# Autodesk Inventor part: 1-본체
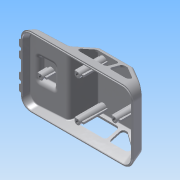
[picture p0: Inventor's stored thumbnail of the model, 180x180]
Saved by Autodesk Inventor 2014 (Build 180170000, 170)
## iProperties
Created: 2015-05
Part Number: 1-본체
Material: ABS 플라스틱
Document SubType Name: Modeling
Designer: Administrator
Density: 1.06 g/cm^3
Appearance: 매끄러움 - 흰색
Mass: 31.9513 g
Surface Area: 305.413 cm^2
Volume: 30.1428 cm^3
Author: Administrator
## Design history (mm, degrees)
sketch "스케치1"
  geometry: L1 (0, 0)-(122, 0); L2 (0, 0)-(2.144, 8); L3 (2.144, 8)-(42, 10.089); L4 (42, 10.089)-(54.442, 30); L5 (54.442, 30)-(92, 30); L6 (92, 30)-(118.738, 12.175); L7 (118.738, 12.175)-(122, 0); L8 (118.738, 12.175)-(122, 10); L9 (122, 10)-(122, 0)
  constraints: 18 end point, 1 collinear, 1 horizontal, 1 parallel, 1 perpendicular
  dimensions: "d0" = 122 distance of L1.start L1.end; "d1" = 8 distance from line of L1 L2.end; "d2" = 105 deg angle of L1 L2; "d3" = 42 horizontal distance of L1.start L3.end; "d4" = 30 horizontal distance of L1.end L5.end; "d6" = 30 horizontal distance of L1.end L5.end; "d7" = 3 deg angle of L1 L3; "d8" = 125 deg angle of L3 L4; "d9" = 20 vertical distance of L8.end L5.end; "d10" = 105 deg angle of L1 L7
extrude "돌출1" new body sketch "스케치1" stored distance "d11" = 76; taper "d12" = 0 deg
sketch "스케치2"
  geometry: L1 (8, 38)-(0, 38) reference; L2 (0, 38)-(0, -38) reference; L3 (0, 38)-(30, 38); L4 (30, 38)-(30, 29.962); L5 (30, 29.962)-(0, 38); L6 (30, -38)-(30, 38) reference; L7 (0, -38)-(30, -29.962); L8 (30, -38)-(0, -38); 1 further point
  constraints: 10 end point, 3 perpendicular, 1 collinear, 1 point on line
  dimensions: "d14" = 105 deg angle of L2 L5; "d51" = 105 deg angle of L2 L7
extrude "돌출2" cut sketch "스케치2" stored distance "d15" = 76; taper "d16" = 0 deg
sketch "스케치9"
  geometry: L1 (8.441, 48.856)-(28.441, 48.856); L2 (28.441, 48.856)-(28.441, 22.856); L3 (28.441, 22.856)-(8.441, 22.856); L4 (8.441, 22.856)-(8.441, 48.856); L5 (-2.559, -2.144)-(-2.559, 73.856) reference; 3 further points
  constraints: 8 end point, 2 midpoint, 2 parallel, 1 horizontal, 1 horizontal alignment, 1 perpendicular
  dimensions: "d59" = 11 distance between parallel lines of L4 L5; "d60" = 20 distance of L1.start L1.end; "d61" = 26 distance of L3.end L1.start
extrude "돌출7" join sketch "스케치9" distance "d62" = 5; taper "d63" = -20 deg
fillet "모깎기1" dims "d18" = 12, "d19" = 3
fillet "모깎기2" dims "d20" = 3
feature "쉘1" dims "d17" = 2
sketch "스케치3"
  geometry: L1 (91.092, 30)-(56.105, 30) reference; L2 (53.561, 28.59)-(42.828, 11.413) reference; L3 (81.84, 25)-(57.213, 25); L4 (57.213, 25)-(47.84, 10); L5 (47.84, 10)-(81.84, 10); L6 (81.84, 10)-(81.84, 25); L7 (84.986, 25)-(84.986, 10); L8 (84.986, 10)-(112.986, 10); L9 (107.213, 19.858)-(92.756, 29.496) reference; L10 (112.986, 10)-(90.486, 25); L11 (84.986, 25)-(90.486, 25); 1 further point
  constraints: 16 end point, 6 parallel, 2 perpendicular, 1 collinear, 1 point on line
  dimensions: "d21" = 5 distance between parallel lines of L4 L2; "d22" = 5 distance between parallel lines of L3 L1; "d23" = 15 distance between parallel lines of L5 L3; "d24" = 34 distance of L4.end L5.end; "d25" = 5 distance between parallel lines of L9 L10; "d26" = 28 distance of L7.end L8.end
extrude "돌출3" cut sketch "스케치3" stored distance "d27" = 0; taper "d28" = 0 deg
fillet "모깎기3" dims "d29" = 3
sketch "스케치5"
  geometry: L1 (0.139, -2.071)-(98.679, -2.071) reference; L2 (108.338, -11.73)-(108.338, -64.27) reference; L3 (-9.521, -64.27)-(-9.521, -11.73) reference; L4 (98.679, -73.929)-(0.139, -73.929) reference; L5 (-10.521, -11.73)-(-10.521, -64.27); L6 (0.139, -74.929)-(98.679, -74.929); L7 (109.338, -64.27)-(109.338, -11.73); L8 (98.679, -1.071)-(0.139, -1.071); 8 further points; 5 other entities
  constraints: 8 end point, 7 parallel, 17 other
  dimensions: "d52" = 1 distance between parallel lines of L3 L5
extrude "돌출4" join sketch "스케치5" distance "d32" = 1; taper "d33" = 0 deg
node "작업 평면1"
sketch "스케치6"
  geometry: L1 (0, 25)-(0, 17); L2 (0, 14)-(0, 6); L3 (0, -6)-(0, -14); L4 (0, -17)-(0, -25); A1 r 4 centre (0, 21) between (0, 25) and (0, 17); A2 r 4 centre (0, 10) between (0, 14) and (0, 6); A3 r 4 centre (0, -10) between (0, -6) and (0, -14); A4 r 4 centre (0, -21) between (0, -17) and (0, -25); 4 further points
  constraints: 8 end point, 8 point on circle, 4 centre point, 13 other
  dimensions: "d35" = 8 diameter of A1; "d36" = 8 diameter of A2; "d37" = 8 diameter of A3; "d38" = 8 diameter of A4; "d39" = 20 distance of A3.centre A2.centre; "d40" = 11 distance of A2.centre A1.centre; "d41" = 11 distance of A4.centre A3.centre; "d42" = 10 distance of point (0, 0) A3.centre
extrude "돌출5" join sketch "스케치6" stored distance "d43" = 1; taper "d44" = 0 deg
chamfer "모따기1" distance "d45" = 1; stored, may be unused: second distance "d46" = 2, angle "d47" = 45 deg
sketch "스케치7"
  geometry: L1 (65.895, 54.068)-(65.895, 1.251) reference; 3 further points
  constraints: 1 horizontal alignment, 1 midpoint, 1 other
  dimensions: "d53" = 50 distance from line of L1 point (15.895, 27.66)
feature "엠보싱1" sketch "스케치7" dims "d49" = 0.5, "d50" = 0
sketch "스케치10"
  geometry: L1 (-11.591, 44)-(-11.591, 32) reference; L2 (110.409, 11.591)-(110.409, 64.409) reference; C1 r 3 at (9.409, 38); C2 r 3 at (89.409, 38); C3 r 3 at (49.409, 16); C4 r 3 at (49.409, 60); 2 further points
  constraints: 4 centre point, 3 equal radius, 2 horizontal alignment, 1 midpoint, 1 vertical alignment
  dimensions: "d64" = 6 diameter of C1; "d65" = 21 distance from line of C2.centre L2; "d66" = 40 horizontal distance of C3.centre C2.centre; "d67" = 22 vertical distance of point (-11.591, 38) C3.centre; "d68" = 44 distance of C3.centre C4.centre; "d69" = 40 horizontal distance of C3.centre C1.centre
extrude "돌출8" join sketch "스케치10" stored distance "d70" = 5; taper "d71" = 2 deg
node "작업 평면2"
sketch "스케치11"
  geometry: L1 (-45, 21)-(-35, 21); L2 (-35, 21)-(-35, 23); L3 (-35, 23)-(-45, 23); L4 (-45, 23)-(-45, 21); L5 (-45, 21)-(-35, 23); L6 (-35, 21)-(-45, 23); L7 (-85, -1)-(-75, -1); L8 (-75, -1)-(-75, 1); L9 (-75, 1)-(-85, 1); L10 (-85, -1)-(-75, 1); L11 (-75, -1)-(-85, 1); L12 (-45, -23)-(-35, -23); L13 (-35, -23)-(-35, -21); L14 (-35, -21)-(-45, -21); L15 (-45, -21)-(-45, -23); L16 (-45, -23)-(-35, -21); L17 (-35, -23)-(-45, -21); L18 (-5, -1)-(5, -1); L19 (5, -1)-(5, 1); L20 (5, 1)-(-5, 1); L21 (-5, 1)-(-5, -1); L22 (-5, -1)-(5, 1); L23 (5, -1)-(-5, 1); L24 (-85, 1)-(-85, -1); C1 r 3 at (-40, 22) reference; C2 r 3 at (-80, 0) reference; C3 r 3 at (-40, -22) reference; C4 r 3 at (0, 0) reference; 1 further point
  constraints: 48 end point, 8 midpoint, 8 parallel, 6 equal length, 4 horizontal, 4 perpendicular
  dimensions: "d73" = 10 distance of L1.start L1.end; "d74" = 2 distance of L1.end L2.end
extrude "돌출11" join sketch "스케치11" stored distance "d93" = 0; taper "d94" = 0 deg
sketch "스케치15"
  geometry: C1 r 3 at (0, 0) reference; C2 r 3 at (-40, -22) reference; C3 r 3 at (0, -44) reference; C4 r 3 at (40, -22) reference; 5 further points
  constraints: 4 coincident
hole "구멍1" sketch "스케치15" at (0, 0), (-40, -22), (0, -44), (40, -22) diameter "d95" = 3.242; stored, may be unused: countersink angle "d99" = 90 deg, drill point angle "d101" = 118 deg; dims "d96" = 9, "d97" = 4, "d98" = 2, "d100" = 11
node "솔리드1"
node "투영된 루프1"
node "투영된 루프2"
node "투영된 루프3"
node "투영된 루프4"
node "투영된 루프5"
node "투영된 루프6"
other parameters: "d34" = -2, "d72" = -2
